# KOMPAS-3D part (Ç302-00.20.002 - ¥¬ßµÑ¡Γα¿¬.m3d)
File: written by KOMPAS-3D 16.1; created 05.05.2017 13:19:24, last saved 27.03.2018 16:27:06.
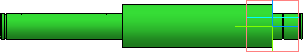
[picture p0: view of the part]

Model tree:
1. Эскиз:1
2. Операция выдавливания:1
     Расстояние 1 = 144.5
3. Эскиз:4
4. Операция выдавливания:3
     Расстояние 1 = 29
5. Смещенная плоскость:1
     Расстояние = 2.3
6. Эскиз:7
7. Вырезать элемент выдавливания:4
     Расстояние 1 = 1.4
8. Фаска:1
     Угол = 45; Длина 1 = 0.5; Длина 2 = 0.5
9. Массив по сетке:1  (with: Вырезать элемент выдавливания:4, Смещенная плоскость:1, Эскиз:7)  (2 pattern instances)
     Шаг 1 = 16.1; Угол раствора = 90; Номер 1 = 1
10. Эскиз:8
11. Операция вращения:1
     Угол 1 = 360
12. Фаска:2
     Угол = 45; Длина 1 = 1; Длина 2 = 1
13. Смещенная плоскость:2
     Расстояние = 8.5
14. Эскиз:9
15. Вырезать элемент выдавливания:5  (labels: Сталь 40Х  ГОСТ 4543-71)
     Расстояние 2 = 4; Расстояние 1 = 4

Expressions: 25/2; 23.5/2; 112+1.3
